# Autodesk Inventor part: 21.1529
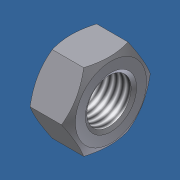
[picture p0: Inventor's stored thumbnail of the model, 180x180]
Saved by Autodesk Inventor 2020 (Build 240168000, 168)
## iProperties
Created: 2006-02
Part Number: 21.1529
Material: Steel, Mild
Description: M16 HEX NUT
Document SubType Name: Modeling
Standard: DIN 934
Designer: Andy Moles
Standards Organization: DIN
Language: en-US
Size Designation: M16
Categories: <MemberInstance><Categories><Category DisplayName="Fasteners" InternalName="e4da775c-781d-43d5-af7c-5136215cf5a6" Mnemonic="FSTN"><Category DisplayName="Nuts" I
Density: 7.85 g/cm^3
Mass: 34.4371 g
Surface Area: 21.9132 cm^2
Volume: 4.38689 cm^3
Appearance: Zinc
Author: Andy Moles
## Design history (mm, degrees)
sketch "Sketch1"
  geometry: L1 (-13.856, 0)-(-6.928, 12); L2 (-6.928, 12)-(6.928, 12); L3 (6.928, 12)-(13.856, 0); L4 (13.856, 0)-(6.928, -12); L5 (6.928, -12)-(-6.928, -12); L6 (-6.928, -12)-(-13.856, 0); 2 further points
  constraints: 12 end point, 1 coincident, 1 horizontal, 11 other
  dimensions: "d0" = 27.71281 distance of L3.end L1.start (= 1.1547 x SW)
extrude "Body" new body sketch "Sketch1" distance "d1" = 13 (= KOH); taper "d2" = 0 deg
sketch "Sketch2"
  geometry: L1 (0, 6.928)-(0, 13.856) reference; L2 (0, 13.856)-(13, 13.856) reference; L3 (13, 6.928)-(13, 13.856) reference; L4 (-1.3, 0)-(16.9, 0) reference; L5 (1.591, 13.856)-(0, 11.1); L6 (11.409, 13.856)-(13, 11.1)
  constraints: 4 end point, 4 point on line
  dimensions: "d3" = 30 deg angle of L1 L5 (= ANG1); "d4" = 30 deg angle of L3 L6 (= ANG2); "d5" = 22.2 diameter of L5.end L4 (= SW0); "d6" = 22.2 diameter of L6.end L4 (= SW01)
revolve "Chamfer1" sketch "Sketch2" stored, may be unused: angle "d7" = 90 deg
sketch "Sketch3"
  geometry: 4 further points
  constraints: 1 coincident, 1 other
hole "Thread" sketch "Sketch3" at (0, 0) diameter "d25" = 13.835; stored, may be unused: countersink angle "d29" = 82 deg, drill point angle "d31" = 118 deg; dims "d26" = 6, "d27" = 4, "d28" = 2, "d30" = 8
workaxis "Work Axis1"
workplane "Work Plane1"
body "Solid1"
chamfer "Chamfer2" distance "d8" = 1.08253 (= -0.5 x GD1 + 0.5 x NND); stored, may be unused: angle "d9" = 30 deg, second distance "d40" = 1.08253 (= -0.5 x GD1 + 0.5 x NND)
chamfer "Chamfer3" distance "d10" = 1.08253 (= -0.5 x GD1 + 0.5 x NND); stored, may be unused: angle "d11" = 30 deg, second distance "d41" = 1.08253 (= -0.5 x GD1 + 0.5 x NND)
other parameters: "ANG1" = 30 deg [user parameter; used in 1 equation term], "ANG2" = 30 deg [user parameter; used in 1 equation term], "NND" = 16 [user parameter; used in 4 equation terms], "KOH" = 13 [user parameter; used in 1 equation term], "SW" = 24 [user parameter; used in 2 equation terms], "SW0" = 22.2 (= SW01) [user parameter; used in 1 equation term], "SW01" = 22.2 [user parameter; used in 2 equation terms], "GD1" = 13.83494 (computed from THREADDIA, PTC, TOA) [user parameter; used in 4 equation terms], "d13" = 0, "d14" = 0, "d39" = 0, "d42" = 0, "GUL" = 1.08253 (= 0.541266 x PTC) [user parameter], "TPU" = 5 (computed from PTC) [user parameter], "THREADDIA" = 16 [user parameter; used in 1 equation term], "TOA" = 30 deg [user parameter; used in 1 equation term], "PTC" = 2 [user parameter; used in 4 equation terms], "E0" = 27.72 (= 1.155 x SW) [user parameter], "GAL" = 1.08253 (= 0.541266 x PTC) [user parameter]
